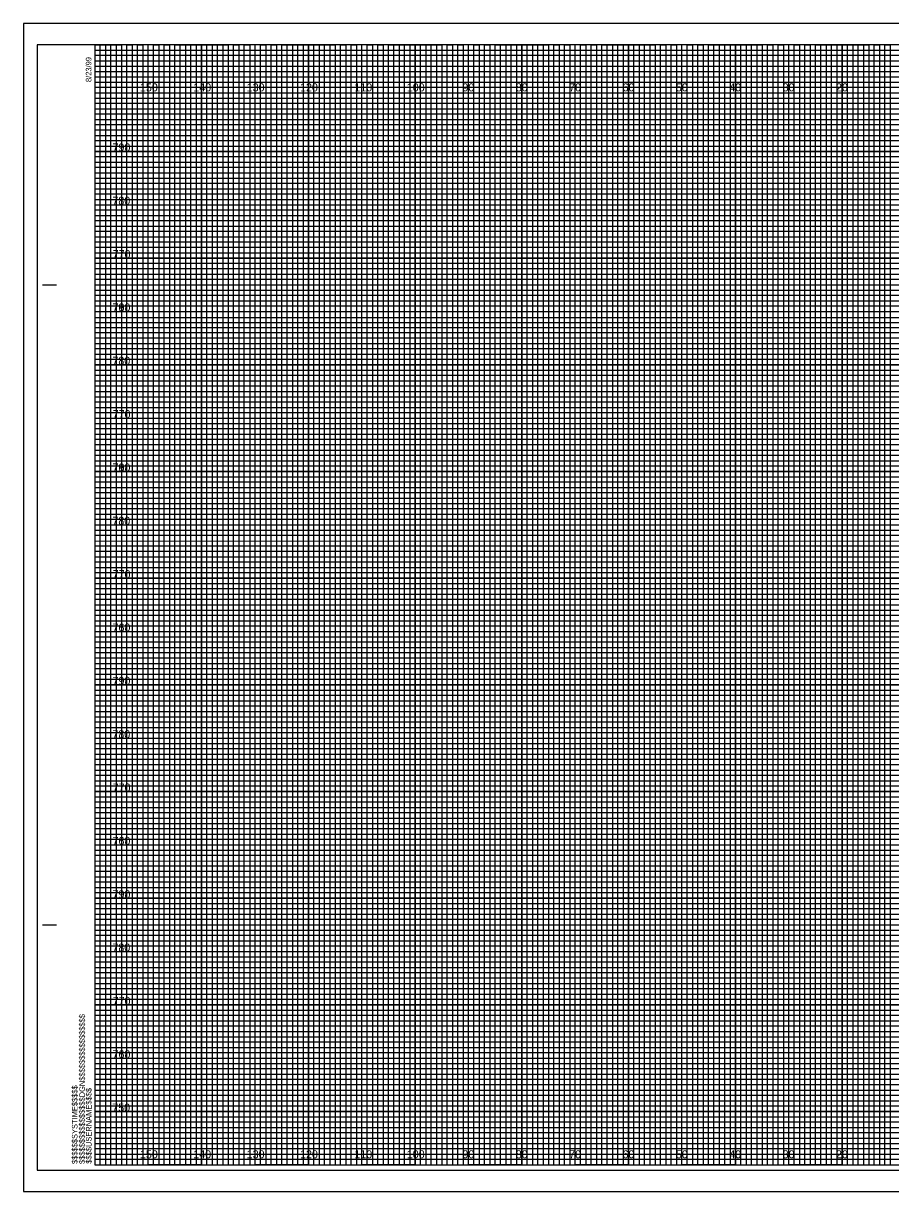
# Model space of a CAD drawing. Extents: x -13 to 323, y 655 to 874.
# Drawn here: x -13.4 to 149.1, y 655 to 874 of the extents above; entities that cross this region are included whole.
import ezdxf

# ---------------------------------------------------------------- set-up
doc = ezdxf.new("R2010")
doc.units = 0
for name, color, linetype in [('Exist Cross Section Cell', 7, 'Continuous'), ('Exist XS Ground Line', 7, 'Continuous'), ('Prop XS Ditch Slope Text', 7, 'Continuous'), ('Prop XS Ditch Standard Text', 7, 'Continuous'), ('Prop XS Dump Level', 7, 'Continuous'), ('Prop XS EOT Tick Mark', 7, 'Continuous'), ('Prop XS Finish Grade', 7, 'Continuous'), ('Prop XS Finish Grade Earthwork', 7, 'Continuous'), ('Prop XS Pvmt Edge Slope', 7, 'Continuous'), ('Prop XS Side Slope Text', 7, 'Continuous'), ('Prop XS Subgrade Earthwork', 7, 'Continuous')]:
    doc.layers.add(name, color=color, linetype=linetype)

msp = doc.modelspace()

# ---------------------------------------------------------------- linework, layer by layer
at = {"layer": 'Exist XS Ground Line'}
for p, q in [((10, 870), (0, 870)), ((10, 660), (10, 870)), ((30, 870), (20, 870)), ((20, 870), (20, 660)), ((30, 660), (30, 870)), ((50, 870), (40, 870)), ((40, 870), (40, 660)), ((50, 660), (50, 870)), ((70, 870), (60, 870)), ((60, 870), (60, 660)), ((70, 660), (70, 870)), ((90, 870), (80, 870)), ((80, 870), (80, 660)), ((90, 660), (90, 870)), ((110, 870), (100, 870)), ((100, 870), (100, 660)), ((110, 660), (110, 870)), ((130, 870), (120, 870)), ((120, 870), (120, 660)), ((130, 660), (130, 870)), ((150, 870), (140, 870)), ((140, 870), (140, 660)), ((20, 660), (10, 660)), ((40, 660), (30, 660)), ((60, 660), (50, 660)), ((80, 660), (70, 660)), ((100, 660), (90, 660)), ((120, 660), (110, 660)), ((140, 660), (130, 660))]:
    msp.add_line(p, q, dxfattribs=at)
for points in [[(0, 860), (320, 860), (320, 850), (0, 850)], [(0, 840), (320, 840), (320, 830), (0, 830)], [(0, 820), (320, 820), (320, 810), (0, 810)], [(0, 800), (320, 800), (320, 790), (0, 790)], [(0, 780), (320, 780), (320, 770), (0, 770)], [(0, 760), (320, 760), (320, 750), (0, 750)], [(0, 740), (320, 740), (320, 730), (0, 730)], [(0, 720), (320, 720), (320, 710), (0, 710)], [(0, 700), (320, 700), (320, 690), (0, 690)], [(0, 680), (320, 680), (320, 670), (0, 670)]]:
    msp.add_lwpolyline(points, dxfattribs=at)
at = {"layer": 'Prop XS Ditch Slope Text'}
for p, q in [((-9.8, 825), (-7.3, 825)), ((-9.7, 825), (-7.2, 825)), ((-9.8, 705), (-7.3, 705)), ((-9.7, 705), (-7.2, 705)), ((0, 660), (0, 660)), ((0, 660), (0, 660)), ((0, 660), (0, 660)), ((0, 660), (0, 660)), ((0, 660), (0, 660)), ((0, 660), (0, 660)), ((0, 660), (0, 660))]:
    msp.add_line(p, q, dxfattribs=at)
msp.add_lwpolyline([(320, 870), (0, 870), (0, 660), (320, 660)], close=True, dxfattribs=at)
at = {"layer": 'Prop XS Ditch Standard Text'}
for p, q in [((0, 869), (260, 869)), ((260, 867.98), (0, 867.98)), ((0, 867.98), (0, 867)), ((0, 867), (260, 867)), ((260, 865.89), (0, 865.89)), ((0, 865.89), (0, 864)), ((0, 864), (320, 864))]:
    msp.add_line(p, q, dxfattribs=at)
for points in [[(0, 863), (270, 863), (320, 863), (320, 862), (0, 862)], [(0, 861), (320, 861), (320, 859), (0, 859)], [(0, 858), (320, 858), (320, 857), (0, 856.98)], [(0, 856), (320, 856), (320, 854), (0, 854)], [(0, 853), (320, 853), (320, 852), (0, 852)], [(0, 851), (320, 851), (320, 849), (0, 849)], [(0, 848), (320, 848), (320, 847), (0, 847)], [(0, 846), (320, 846), (320, 844), (0, 844)], [(0, 843), (320, 843), (320, 842), (0, 842)], [(0, 841), (320, 841), (320, 839), (0, 839)], [(0, 838), (320, 838), (320, 837), (0, 837)], [(0, 836), (320, 836), (320, 833.95), (320, 833), (320, 832), (0, 832)], [(0, 834), (320, 834), (320, 833), (0, 833)], [(0, 831), (320, 831), (320, 829), (0, 829.03)], [(0, 829.03), (320, 829), (320, 828), (0, 828)], [(0, 827), (320, 827), (320, 826), (0, 826)], [(0, 824), (320, 824), (320, 823), (0, 823)], [(0, 822), (320, 822), (320, 821), (0, 821)], [(-0.07, 818.89), (320, 818.89), (320, 817.88), (-0.07, 817.88)], [(0, 817), (320, 817), (320, 816), (0, 816)], [(0, 814), (320, 814), (320, 813), (0, 813)], [(0, 812), (320, 812), (320, 811), (0, 811)], [(0, 809), (320, 809), (320, 808), (0, 808)], [(0, 807), (320, 807), (320, 806), (0, 806)], [(0, 804), (320, 804), (320, 803), (0, 803)], [(0, 802), (320, 802), (320, 801), (0, 801)], [(0, 799), (320, 799), (319.99, 797.98), (0, 798)], [(0, 797), (320, 797), (320, 796), (0, 796)], [(0, 794), (320, 794), (320, 793), (0, 793)], [(0, 792), (320, 792), (320, 791), (0, 791)], [(0, 789), (320, 789), (320, 788), (0, 788)], [(0, 787), (320, 787), (320, 786), (0, 786)], [(0, 784), (320, 784), (320, 783), (0, 783)], [(0, 782), (320, 782), (320, 781), (0, 781)], [(0, 779), (320, 779), (320, 778), (0, 778)], [(0, 776.99), (320.07, 776.91), (320, 776), (0, 776)], [(0, 774), (320, 774), (320, 773), (0, 773)], [(0, 772), (320, 772), (320, 771), (0, 771)], [(0, 769), (320, 769), (320, 768), (0, 768)], [(0, 767), (320, 767), (320, 766), (0, 766)], [(0, 764), (320, 764), (320, 763), (0, 763)], [(0, 762), (320, 762), (320, 761), (0, 761)], [(0, 759), (320, 759), (320, 758), (0, 758)], [(0, 757), (320, 757), (320, 756), (0, 756)], [(0, 754), (320, 754), (320, 753), (0, 753)], [(0, 752), (320, 752), (320, 751), (0, 751)], [(0, 749), (320, 749), (320, 748), (0, 748)], [(0, 747), (320, 747), (320, 746), (0, 746)], [(0, 744), (320, 744), (320, 743), (0, 743)], [(0, 742), (320, 742), (320, 741), (0, 741)], [(0, 739), (320, 739), (319.99, 737.98), (0, 738)], [(0, 737), (320, 737), (320, 736), (0, 736)], [(0, 734), (320, 734), (320, 733), (0, 733)], [(0, 732), (320, 732), (320, 731), (0, 731)], [(0, 729), (320, 729), (320, 728), (0, 728)], [(0, 727), (320, 727), (320, 726), (0, 726)], [(0, 724), (320, 724), (320, 723), (0, 723)], [(0, 722), (320, 722), (320, 721), (0, 721)], [(0, 719), (320, 719), (320, 718), (0, 718)], [(0, 716.99), (320.07, 716.91), (320, 716), (0, 716)], [(0, 714), (320, 714), (320, 713), (0, 713)], [(0, 712), (320, 712), (320, 711), (0, 711)], [(0, 709), (320, 709), (320, 708), (0, 708)], [(0, 707), (320, 707), (320, 706), (0, 706)], [(0, 704), (320, 704), (320, 703), (0, 703)], [(0, 702), (320, 702), (320, 701), (0, 701)], [(0, 699), (320, 699), (320, 698), (0, 698)], [(0, 697), (320, 697), (320, 696), (0, 696)], [(0, 694), (320, 694), (320, 693), (0, 693)], [(0, 692), (320, 692), (320, 691), (0, 691)], [(0, 689), (320, 689), (320, 688), (0, 688)], [(0, 687), (320, 687), (320, 686), (0, 686)], [(0, 684), (320, 684), (320, 683), (0, 683)], [(0, 682), (320, 682), (320, 681), (0, 681)], [(0, 679), (320, 679), (320, 678), (0, 678)], [(0, 677), (320, 677), (320, 676), (0, 676)], [(0, 674), (320, 674), (320, 673), (0, 673)], [(0, 672), (320, 672), (320, 671), (0, 671)], [(0, 669), (320, 669), (320, 668), (0, 668)], [(0, 667), (320, 667), (320, 666), (0, 666)], [(0, 664), (320, 664), (320, 663), (0, 663)], [(0, 662), (320, 662), (320, 661), (0, 661)]]:
    msp.add_lwpolyline(points, dxfattribs=at)
at = {"layer": 'Prop XS Dump Level'}
for points in [[(0, 870), (5, 870), (5, 660), (15, 660), (15, 870), (25, 870), (25, 660), (35, 660), (35, 870), (45, 870), (45, 660), (55, 660), (55, 870), (65, 870), (65, 660), (75, 660), (75, 870), (85, 870), (85, 660), (95, 660), (95, 870), (105, 870), (105, 660), (115, 660), (115, 870), (125, 870), (125, 660), (135, 660), (135, 870), (145, 870), (145, 660), (155, 660)], [(0, 865), (275, 865)], [(0, 845), (320, 845), (320, 855), (0, 855)], [(0, 825), (320, 825), (320, 835), (0, 835)], [(0, 805), (320, 805), (320, 815), (0, 815)], [(0, 785), (320, 785), (320, 795), (0, 795)], [(0, 765), (320, 765), (320, 775), (0, 775)], [(0, 745), (320, 745), (320, 755), (0, 755)], [(0, 725), (320, 725), (320, 735), (0, 735)], [(0, 705), (320, 705), (320, 715), (0, 715)], [(0, 685), (320, 685), (320, 695), (0, 695)], [(0, 665), (320, 665), (320, 675), (0, 675)]]:
    msp.add_lwpolyline(points, dxfattribs=at)
at = {"layer": 'Prop XS Finish Grade'}
for p, q in [((10, 660), (10, 870)), ((20, 660), (20, 870)), ((30, 660), (30, 870)), ((40, 660), (40, 870)), ((50, 660), (50, 870)), ((60, 660), (60, 870)), ((70, 660), (70, 870)), ((80, 660), (80, 870)), ((90, 660), (90, 870)), ((100, 660), (100, 870)), ((110, 660), (110, 870)), ((120, 660), (120, 870)), ((130, 660), (130, 870)), ((140, 660), (140, 870)), ((0, 860), (320, 860)), ((0, 850), (320, 850)), ((0, 840), (320, 840)), ((0, 830), (320, 830)), ((0, 820), (320, 820)), ((0, 810), (320, 810)), ((0, 800), (320, 800)), ((0, 790), (320, 790)), ((0, 780), (320, 780)), ((0, 770), (320, 770)), ((0, 760), (320, 760)), ((0, 750), (320, 750)), ((0, 740), (320, 740)), ((0, 730), (320, 730)), ((0, 720), (320, 720)), ((0, 710), (320, 710)), ((0, 700), (320, 700)), ((0, 690), (320, 690)), ((0, 680), (320, 680)), ((0, 670), (320, 670))]:
    msp.add_line(p, q, dxfattribs=at)
at = {"layer": 'Prop XS Finish Grade Earthwork'}
msp.add_lwpolyline([(-13.4, 655), (323.3, 655), (323.3, 874), (-13.4, 874)], close=True, dxfattribs=at)
at = {"layer": 'Prop XS Pvmt Edge Slope'}
for p, q in [((323.3, 874), (-13.4, 874)), ((-13.4, 874), (-13.4, 655)), ((-13.4, 655), (323.3, 655))]:
    msp.add_line(p, q, dxfattribs=at)
at = {"layer": 'Prop XS Side Slope Text'}
for points in [[(0, 660), (1, 660), (1, 870), (2, 870), (2, 660)], [(2, 660), (3, 660), (3, 870), (4, 870), (4, 660)], [(5, 660), (6, 660), (6, 870), (7, 870), (7, 660)], [(7, 660), (8, 660), (8, 870), (9, 870), (9, 660)], [(10, 660), (11, 660), (11, 870), (12, 870), (12, 660)], [(12, 660), (13, 660), (13, 870), (14, 870), (14, 660)], [(15, 660), (16, 660), (16, 870), (17, 870), (17, 660)], [(17, 660), (18, 660), (18, 870), (19, 870), (19, 660)], [(20, 660), (21, 660), (21, 870), (22, 870), (22, 660)], [(22, 660), (23, 660), (23, 870), (24, 870), (24, 660)], [(25, 660), (26, 660), (26, 870), (27, 870), (27, 660)], [(27, 660), (28, 660), (28, 870), (29, 870), (29, 660)], [(30, 660), (31, 660), (31, 870), (32, 870), (32, 660)], [(32, 660), (33, 660), (33, 870), (34, 870), (34, 660)], [(35, 660), (36, 660), (36, 870), (37, 870), (37, 660)], [(37, 660), (38, 660), (38, 870), (39, 870), (39, 660)], [(40, 660), (41, 660), (41, 870), (42, 870), (42, 660)], [(42, 660), (43, 660), (43, 870), (44, 870), (44, 660)], [(45, 660), (46, 660), (46, 870), (47, 870), (47, 660)], [(47, 660), (48, 660), (48, 870), (49, 870), (49, 660)], [(50, 660), (51, 660), (51, 870), (52, 870), (52, 660)], [(52, 660), (53, 660), (53, 870), (54, 870), (54, 660)], [(55, 660), (56, 660), (56, 870), (57, 870), (57, 660)], [(57, 660), (58, 660), (58, 870), (59, 870), (59, 660)], [(60, 660), (61, 660), (61, 870), (62, 870), (62, 660)], [(62, 660), (63, 660), (63, 870), (64, 870), (64, 660)], [(65, 660), (66, 660), (66, 870), (67, 870), (67, 660)], [(67, 660), (68, 660), (68, 870), (69, 870), (69, 660)], [(70, 660), (71, 660), (71, 870), (72, 870), (72, 660)], [(72, 660), (73, 660), (73, 870), (74, 870), (74, 660)], [(75, 660), (76, 660), (76, 870), (77, 870), (77, 660)], [(77, 660), (78, 660), (78, 870), (79, 870), (79, 660)], [(80, 660), (81, 660), (81, 870), (82, 870), (82, 660)], [(82, 660), (83, 660), (83, 870), (84, 870), (84, 660)], [(85, 660), (86, 660), (86, 870), (87, 870), (87, 660)], [(87, 660), (88, 660), (88, 870), (89, 870), (89, 660)], [(90, 660), (91, 660), (91, 870), (92, 870), (92, 660)], [(92, 660), (93, 660), (93, 870), (94, 870), (94, 660)], [(95, 660), (96, 660), (96, 870), (97, 870), (97, 660)], [(97, 660), (98, 660), (98, 870), (99, 870), (99, 660)], [(100, 660), (101, 660), (101, 870), (102, 870), (102, 660)], [(102, 660), (103, 660), (103, 870), (104, 870), (104, 660)], [(105, 660), (106, 660), (106, 870), (107, 870), (107, 660)], [(107, 660), (108, 660), (108, 870), (109, 870), (109, 660)], [(110, 660), (111, 660), (111, 870), (112, 870), (112, 660)], [(112, 660), (113, 660), (113, 870), (114, 870), (114, 660)], [(115, 660), (116, 660), (116, 870), (117, 870), (117, 660)], [(117, 660), (118, 660), (118, 870), (119, 870), (119, 660)], [(120, 660), (121, 660), (121, 870), (122, 870), (122, 660)], [(122, 660), (123, 660), (123, 870), (124, 870), (124, 660)], [(125, 660), (126, 660), (126, 870), (127, 870), (127, 660)], [(127, 660), (128, 660), (128, 870), (129, 870), (129, 660)], [(130, 660), (131, 660), (131, 870), (132, 870), (132, 660)], [(132, 660), (133, 660), (133, 870), (134, 870), (134, 660)], [(135, 660), (136, 660), (136, 870), (137, 870), (137, 660)], [(137, 660), (138, 660), (138, 870), (139, 870), (139, 660)], [(140, 660), (141, 660), (141, 870), (142, 870), (142, 660)], [(142, 660), (143, 660), (143, 870), (144, 870), (144, 660)], [(145, 660), (146, 660), (146, 870), (147, 870), (147, 660)], [(147, 660), (148, 660), (148, 870), (149, 870), (149, 660)]]:
    msp.add_lwpolyline(points, dxfattribs=at)
at = {"layer": 'Prop XS Subgrade Earthwork'}
msp.add_lwpolyline([(-10.8, 659), (322.4, 659), (322.4, 870), (-10.8, 870)], close=True, dxfattribs=at)

# ---------------------------------------------------------------- texts
at = {"layer": 'Exist Cross Section Cell'}
for s, p in [('150', (8.44, 861.25)), ('140', (18.44, 861.25)), ('130', (28.44, 861.25)), ('120', (38.44, 861.25)), ('110', (48.62, 861.25)), ('100', (58.44, 861.25)), ('90', (68.86, 861.25)), ('80', (78.86, 861.25)), ('70', (88.86, 861.25)), ('60', (98.86, 861.25)), ('50', (108.86, 861.25)), ('40', (118.86, 861.25)), ('30', (128.86, 861.25)), ('20', (138.86, 861.25)), ('150', (8.44, 661.25)), ('140', (18.44, 661.25)), ('130', (28.44, 661.25)), ('120', (38.44, 661.25)), ('110', (48.62, 661.25)), ('100', (58.44, 661.25)), ('90', (68.86, 661.25)), ('80', (78.86, 661.25)), ('70', (88.86, 661.25)), ('60', (98.86, 661.25)), ('50', (108.86, 661.25)), ('40', (118.86, 661.25)), ('30', (128.86, 661.25)), ('20', (138.86, 661.25))]:
    msp.add_text(s, height=1.5, dxfattribs=at).set_placement(p)
at = {"layer": 'Prop XS Ditch Slope Text'}
for s, p in [('8/23/99', (-0.65, 863)), ('$$$$$$$$$$$$$$$$DGN$$$$$$$$$$$$$$$$', (-1.88, 660.18)), ('$$$$$$SYSTIME$$$$$', (-3.26, 660.18)), ('$$$$USERNAME$$$$', (-0.62, 660.23))]:
    msp.add_text(s, height=1.05, rotation=90, dxfattribs=at).set_placement(p)
at = {"layer": 'Prop XS EOT Tick Mark'}
for s, p in [('790', (3.3, 850)), ('780', (3.28, 840)), ('770', (3.33, 830)), ('790', (3.3, 820)), ('760', (3.3, 820)), ('780', (3.28, 810)), ('770', (3.33, 800)), ('790', (3.3, 790)), ('760', (3.3, 790)), ('780', (3.28, 780)), ('770', (3.33, 770)), ('760', (3.3, 760)), ('790', (3.3, 750)), ('780', (3.28, 740)), ('770', (3.33, 730)), ('760', (3.3, 720)), ('790', (3.3, 710)), ('780', (3.28, 700)), ('770', (3.33, 690)), ('760', (3.3, 680)), ('750', (3.25, 670))]:
    msp.add_text(s, height=1.5, dxfattribs=at).set_placement(p)

doc.saveas('drawing.dxf')
